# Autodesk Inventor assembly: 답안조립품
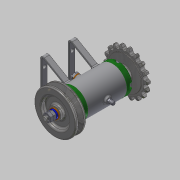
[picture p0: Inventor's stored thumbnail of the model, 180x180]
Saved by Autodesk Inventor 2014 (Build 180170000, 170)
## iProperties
Created: 2016-03
Part Number: 답안조립품
Document SubType Name: Assembly
Designer: SCD-A15
Author: SCD-A15
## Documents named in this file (16)
- C:\Users\SCD-A15\Desktop\460307v1001\답안조립품.iam
- C:\Users\SCD-A15\Desktop\460307v1001\1.본체.ipt
- C:\Users\SCD-A15\Desktop\460307v1001\베어링 15 x 32 x 9.ipt
- C:\Users\SCD-A15\Desktop\460307v1001\커버.ipt
- C:\Users\SCD-A15\Desktop\460307v1001\오일 실 15 25 7.ipt
- C:\Users\SCD-A15\Desktop\460307v1001\볼트 M4 x 12.ipt
- C:\Users\SCD-A15\Desktop\460307v1001\V벨트풀리.ipt
- C:\Users\SCD-A15\Desktop\460307v1001\축.ipt
- C:\Users\SCD-A15\Desktop\460307v1001\키 3 x 3 x 12.ipt
- C:\Users\SCD-A15\Desktop\460307v1001\와셔 8x17.ipt
- C:\Users\SCD-A15\Desktop\460307v1001\스프링와셔 8.ipt
- C:\Users\SCD-A15\Desktop\460307v1001\너트 M 8.ipt
- C:\Users\SCD-A15\Desktop\460307v1001\스프로킷.ipt
- C:\Users\SCD-A15\Desktop\460307v1001\볼트 M 6 x 8.ipt
- C:\Users\SCD-A15\Desktop\460307v1001\와셔 6x11.5.ipt
- C:\Users\SCD-A15\Desktop\460307v1001\니플 M 6 x 0.75.ipt
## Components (12 placed, 4 different names)
1. 1.본체:1
2. KS B 2023 6002 - 15 x 32 x 9:1
3. KS B 2023 6002 - 15 x 32 x 9:2
4. V벨트풀리:1 — 각도:2
5. ISO 4762 M4 x 12:1
6. ISO 4762 M4 x 12:2
7. ISO 4762 M4 x 12:3
8. ISO 4762 M4 x 12:4
9. ISO 4762 M4 x 12:5
10. ISO 4762 M4 x 12:6
11. ISO 4762 M4 x 12:7
12. ISO 4762 M4 x 12:8
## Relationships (1: Angle 1)
- 각도:2 [Angle]: V벨트풀리:1
